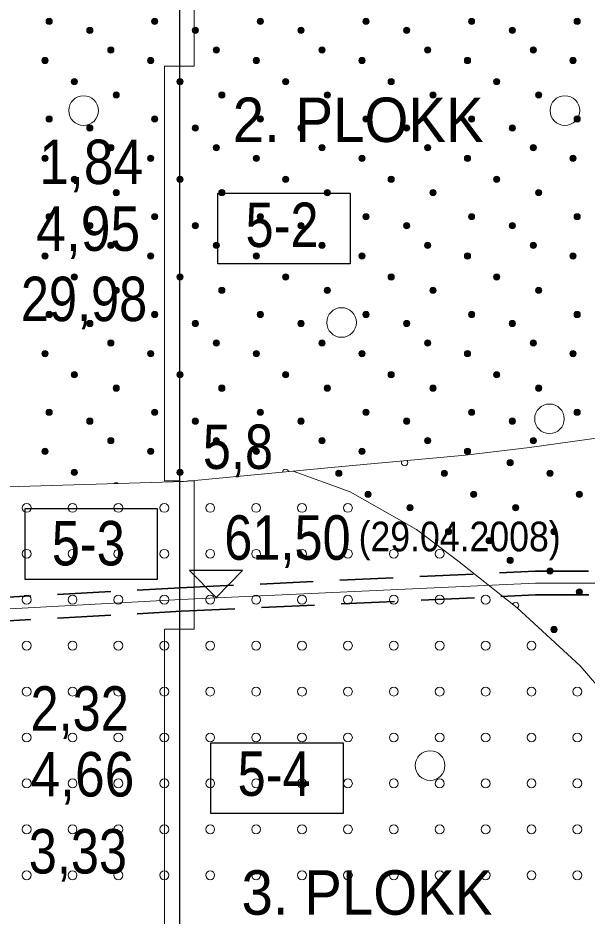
# Model space of a CAD drawing. Extents: x 640121 to 640955, y 6441885 to 6442246.
# Drawn here: x 640200.9 to 640239.3, y 6441932 to 6441992.7 of the extents above; entities that cross this region are included whole.
import ezdxf
from ezdxf.enums import TextEntityAlignment as Align

# ---------------------------------------------------------------- set-up
doc = ezdxf.new("R2010")
doc.units = 0
doc.header["$LTSCALE"] = 1.2
doc.linetypes.add('MEDIUM_DASHED', pattern=[4.5, 3, -1.5])
for name, color, linetype, lineweight in [('31', 7, 'Continuous', 13), ('32', 7, 'Continuous', 13), ('33', 7, 'Continuous', 13), ('34', 7, 'Continuous', 25), ('35', 7, 'Continuous', 35), ('43', 7, 'Continuous', 13), ('44', 7, 'Continuous', 13), ('47', 7, 'Continuous', 13)]:
    doc.layers.add(name, color=color, linetype=linetype, lineweight=lineweight)

msp = doc.modelspace()

# ---------------------------------------------------------------- hatches: boundary and pattern name
at = {"layer": '44'}
for points in [[(640203.218, 6441992.434, 1), (640202.798, 6441992.434, 1)], [(640210.351, 6441992.434, 1), (640209.931, 6441992.434, 1)], [(640217.484, 6441992.434, 1), (640217.064, 6441992.434, 1)], [(640224.617, 6441992.434, 1), (640224.197, 6441992.434, 1)], [(640231.75, 6441992.434, 1), (640231.33, 6441992.434, 1)], [(640238.883, 6441992.434, 1), (640238.463, 6441992.434, 1)], [(640205.965, 6441991.828, 1), (640205.545, 6441991.828, 1)], [(640213.098, 6441991.828, 1), (640212.678, 6441991.828, 1)], [(640220.231, 6441991.828, 1), (640219.811, 6441991.828, 1)], [(640227.364, 6441991.828, 1), (640226.944, 6441991.828, 1)], [(640234.497, 6441991.828, 1), (640234.077, 6441991.828, 1)], [(640207.384, 6441990.506, 1), (640206.964, 6441990.506, 1)], [(640214.517, 6441990.506, 1), (640214.097, 6441990.506, 1)], [(640221.65, 6441990.506, 1), (640221.23, 6441990.506, 1)], [(640228.783, 6441990.506, 1), (640228.363, 6441990.506, 1)], [(640235.916, 6441990.506, 1), (640235.496, 6441990.506, 1)], [(640202.944, 6441989.79, 1), (640202.524, 6441989.79, 1)], [(640210.077, 6441989.79, 1), (640209.657, 6441989.79, 1)], [(640217.21, 6441989.79, 1), (640216.79, 6441989.79, 1)], [(640224.343, 6441989.79, 1), (640223.923, 6441989.79, 1)], [(640231.476, 6441989.79, 1), (640231.056, 6441989.79, 1)], [(640238.609, 6441989.79, 1), (640238.189, 6441989.79, 1)], [(640204.921, 6441988.371, 1), (640204.501, 6441988.371, 1)], [(640212.054, 6441988.371, 1), (640211.634, 6441988.371, 1)], [(640219.187, 6441988.371, 1), (640218.767, 6441988.371, 1)], [(640226.32, 6441988.371, 1), (640225.9, 6441988.371, 1)], [(640233.453, 6441988.371, 1), (640233.033, 6441988.371, 1)], [(640207.748, 6441987.463, 1), (640207.328, 6441987.463, 1)], [(640214.881, 6441987.463, 1), (640214.461, 6441987.463, 1)], [(640222.014, 6441987.463, 1), (640221.594, 6441987.463, 1)], [(640229.147, 6441987.463, 1), (640228.727, 6441987.463, 1)], [(640236.28, 6441987.463, 1), (640235.86, 6441987.463, 1)], [(640203.218, 6441985.838, 1), (640202.798, 6441985.838, 1)], [(640210.351, 6441985.838, 1), (640209.931, 6441985.838, 1)], [(640217.484, 6441985.838, 1), (640217.064, 6441985.838, 1)], [(640224.617, 6441985.838, 1), (640224.197, 6441985.838, 1)], [(640231.75, 6441985.838, 1), (640231.33, 6441985.838, 1)], [(640238.883, 6441985.838, 1), (640238.463, 6441985.838, 1)], [(640205.965, 6441985.232, 1), (640205.545, 6441985.232, 1)], [(640213.098, 6441985.232, 1), (640212.678, 6441985.232, 1)], [(640220.231, 6441985.232, 1), (640219.811, 6441985.232, 1)], [(640227.364, 6441985.232, 1), (640226.944, 6441985.232, 1)], [(640234.497, 6441985.232, 1), (640234.077, 6441985.232, 1)], [(640207.384, 6441983.91, 1), (640206.964, 6441983.91, 1)], [(640214.517, 6441983.91, 1), (640214.097, 6441983.91, 1)], [(640221.65, 6441983.91, 1), (640221.23, 6441983.91, 1)], [(640228.783, 6441983.91, 1), (640228.363, 6441983.91, 1)], [(640235.916, 6441983.91, 1), (640235.496, 6441983.91, 1)], [(640202.944, 6441983.194, 1), (640202.524, 6441983.194, 1)], [(640210.077, 6441983.194, 1), (640209.657, 6441983.194, 1)], [(640217.21, 6441983.194, 1), (640216.79, 6441983.194, 1)], [(640224.343, 6441983.194, 1), (640223.923, 6441983.194, 1)], [(640231.476, 6441983.194, 1), (640231.056, 6441983.194, 1)], [(640238.609, 6441983.194, 1), (640238.189, 6441983.194, 1)], [(640204.921, 6441981.775, 1), (640204.501, 6441981.775, 1)], [(640212.054, 6441981.775, 1), (640211.634, 6441981.775, 1)], [(640219.187, 6441981.775, 1), (640218.767, 6441981.775, 1)], [(640226.32, 6441981.775, 1), (640225.9, 6441981.775, 1)], [(640233.453, 6441981.775, 1), (640233.033, 6441981.775, 1)], [(640207.748, 6441980.867, 1), (640207.328, 6441980.867, 1)], [(640214.881, 6441980.867, 1), (640214.461, 6441980.867, 1)], [(640222.014, 6441980.867, 1), (640221.594, 6441980.867, 1)], [(640229.147, 6441980.867, 1), (640228.727, 6441980.867, 1)], [(640236.28, 6441980.867, 1), (640235.86, 6441980.867, 1)], [(640203.218, 6441979.242, 1), (640202.798, 6441979.242, 1)], [(640210.351, 6441979.242, 1), (640209.931, 6441979.242, 1)], [(640217.484, 6441979.242, 1), (640217.064, 6441979.242, 1)], [(640224.617, 6441979.242, 1), (640224.197, 6441979.242, 1)], [(640231.75, 6441979.242, 1), (640231.33, 6441979.242, 1)], [(640238.883, 6441979.242, 1), (640238.463, 6441979.242, 1)], [(640205.965, 6441978.636, 1), (640205.545, 6441978.636, 1)], [(640213.098, 6441978.636, 1), (640212.678, 6441978.636, 1)], [(640220.231, 6441978.636, 1), (640219.811, 6441978.636, 1)], [(640227.364, 6441978.636, 1), (640226.944, 6441978.636, 1)], [(640234.497, 6441978.636, 1), (640234.077, 6441978.636, 1)], [(640207.384, 6441977.314, 1), (640206.964, 6441977.314, 1)], [(640214.517, 6441977.314, 1), (640214.097, 6441977.314, 1)], [(640221.65, 6441977.314, 1), (640221.23, 6441977.314, 1)], [(640228.783, 6441977.314, 1), (640228.363, 6441977.314, 1)], [(640235.916, 6441977.314, 1), (640235.496, 6441977.314, 1)], [(640202.944, 6441976.598, 1), (640202.524, 6441976.598, 1)], [(640210.077, 6441976.598, 1), (640209.657, 6441976.598, 1)], [(640217.21, 6441976.598, 1), (640216.79, 6441976.598, 1)], [(640224.343, 6441976.598, 1), (640223.923, 6441976.598, 1)], [(640231.476, 6441976.598, 1), (640231.056, 6441976.598, 1)], [(640238.609, 6441976.598, 1), (640238.189, 6441976.598, 1)], [(640204.921, 6441975.179, 1), (640204.501, 6441975.179, 1)], [(640212.054, 6441975.179, 1), (640211.634, 6441975.179, 1)], [(640219.187, 6441975.179, 1), (640218.767, 6441975.179, 1)], [(640226.32, 6441975.179, 1), (640225.9, 6441975.179, 1)], [(640233.453, 6441975.179, 1), (640233.033, 6441975.179, 1)], [(640207.748, 6441974.271, 1), (640207.328, 6441974.271, 1)], [(640214.881, 6441974.271, 1), (640214.461, 6441974.271, 1)], [(640222.014, 6441974.271, 1), (640221.594, 6441974.271, 1)], [(640229.147, 6441974.271, 1), (640228.727, 6441974.271, 1)], [(640236.28, 6441974.271, 1), (640235.86, 6441974.271, 1)], [(640203.218, 6441972.646, 1), (640202.798, 6441972.646, 1)], [(640210.351, 6441972.646, 1), (640209.931, 6441972.646, 1)], [(640217.484, 6441972.646, 1), (640217.064, 6441972.646, 1)], [(640224.617, 6441972.646, 1), (640224.197, 6441972.646, 1)], [(640231.75, 6441972.646, 1), (640231.33, 6441972.646, 1)], [(640238.883, 6441972.646, 1), (640238.463, 6441972.646, 1)], [(640205.965, 6441972.04, 1), (640205.545, 6441972.04, 1)], [(640213.098, 6441972.04, 1), (640212.678, 6441972.04, 1)], [(640220.231, 6441972.04, 1), (640219.811, 6441972.04, 1)], [(640227.364, 6441972.04, 1), (640226.944, 6441972.04, 1)], [(640234.497, 6441972.04, 1), (640234.077, 6441972.04, 1)], [(640207.384, 6441970.718, 1), (640206.964, 6441970.718, 1)], [(640214.517, 6441970.718, 1), (640214.097, 6441970.718, 1)], [(640221.65, 6441970.718, 1), (640221.23, 6441970.718, 1)], [(640228.783, 6441970.718, 1), (640228.363, 6441970.718, 1)], [(640235.916, 6441970.718, 1), (640235.496, 6441970.718, 1)], [(640202.944, 6441970.002, 1), (640202.524, 6441970.002, 1)], [(640210.077, 6441970.002, 1), (640209.657, 6441970.002, 1)], [(640217.21, 6441970.002, 1), (640216.79, 6441970.002, 1)], [(640224.343, 6441970.002, 1), (640223.923, 6441970.002, 1)], [(640231.476, 6441970.002, 1), (640231.056, 6441970.002, 1)], [(640238.609, 6441970.002, 1), (640238.189, 6441970.002, 1)], [(640204.921, 6441968.583, 1), (640204.501, 6441968.583, 1)], [(640212.054, 6441968.583, 1), (640211.634, 6441968.583, 1)], [(640219.187, 6441968.583, 1), (640218.767, 6441968.583, 1)], [(640226.32, 6441968.583, 1), (640225.9, 6441968.583, 1)], [(640233.453, 6441968.583, 1), (640233.033, 6441968.583, 1)], [(640207.748, 6441967.675, 1), (640207.328, 6441967.675, 1)], [(640214.881, 6441967.675, 1), (640214.461, 6441967.675, 1)], [(640222.014, 6441967.675, 1), (640221.594, 6441967.675, 1)], [(640229.147, 6441967.675, 1), (640228.727, 6441967.675, 1)], [(640236.28, 6441967.675, 1), (640235.86, 6441967.675, 1)], [(640203.218, 6441966.05, 1), (640202.798, 6441966.05, 1)], [(640210.351, 6441966.05, 1), (640209.931, 6441966.05, 1)], [(640217.484, 6441966.05, 1), (640217.064, 6441966.05, 1)], [(640224.617, 6441966.05, 1), (640224.197, 6441966.05, 1)], [(640231.75, 6441966.05, 1), (640231.33, 6441966.05, 1)], [(640238.883, 6441966.05, 1), (640238.463, 6441966.05, 1)], [(640205.965, 6441965.444, 1), (640205.545, 6441965.444, 1)], [(640213.098, 6441965.444, 1), (640212.678, 6441965.444, 1)], [(640220.231, 6441965.444, 1), (640219.811, 6441965.444, 1)], [(640227.364, 6441965.444, 1), (640226.944, 6441965.444, 1)], [(640234.497, 6441965.444, 1), (640234.077, 6441965.444, 1)], [(640207.384, 6441964.122, 1), (640206.964, 6441964.122, 1)], [(640214.517, 6441964.122, 1), (640214.097, 6441964.122, 1)], [(640221.65, 6441964.122, 1), (640221.23, 6441964.122, 1)], [(640228.783, 6441964.122, 1), (640228.363, 6441964.122, 1)], [(640235.916, 6441964.122, 1), (640235.496, 6441964.122, 1)], [(640202.944, 6441963.406, 1), (640202.524, 6441963.406, 1)], [(640210.077, 6441963.406, 1), (640209.657, 6441963.406, 1)], [(640217.21, 6441963.406, 1), (640216.79, 6441963.406, 1)], [(640224.343, 6441963.406, 1), (640223.923, 6441963.406, 1)], [(640231.476, 6441963.406, 1), (640231.056, 6441963.406, 1)], [(640234.359, 6441962.648, 1), (640233.939, 6441962.648, 1)], [(640204.921, 6441961.987, 1), (640204.501, 6441961.987, 1)], [(640212.054, 6441961.987, 1), (640211.634, 6441961.987, 1)], [(640222.786, 6441961.932, 1), (640222.366, 6441961.932, 1)], [(640229.919, 6441961.932, 1), (640229.499, 6441961.932, 1)], [(640237.052, 6441961.932, 1), (640236.632, 6441961.932, 1)], [(640224.763, 6441960.513, 1), (640224.343, 6441960.513, 1)], [(640231.896, 6441960.513, 1), (640231.476, 6441960.513, 1)], [(640239.029, 6441960.513, 1), (640238.609, 6441960.513, 1)], [(640227.59, 6441959.605, 1), (640227.17, 6441959.605, 1)], [(640234.723, 6441959.605, 1), (640234.303, 6441959.605, 1)], [(640230.193, 6441957.98, 1), (640229.773, 6441957.98, 1)], [(640237.326, 6441957.98, 1), (640236.906, 6441957.98, 1)], [(640232.94, 6441957.374, 1), (640232.52, 6441957.374, 1)], [(640234.359, 6441956.052, 1), (640233.939, 6441956.052, 1)], [(640237.052, 6441955.336, 1), (640236.632, 6441955.336, 1)], [(640239.029, 6441953.917, 1), (640238.609, 6441953.917, 1)], [(640237.326, 6441951.384, 1), (640236.906, 6441951.384, 1)]]:
    msp.add_hatch(color=256, dxfattribs=at).paths.add_polyline_path(points)

# ---------------------------------------------------------------- linework, layer by layer
at = {"layer": '31'}
for points in [[(640160.01, 6441959.79), (640212.12, 6441961.38), (640223.03, 6441962.4), (640231.14, 6441963.16), (640235.45, 6441963.66), (640242.38, 6441964.64), (640247.49, 6441965.44), (640252.3, 6441966.45), (640254.5, 6441966.85), (640259.39, 6441967.38), (640264.58, 6441967.44), (640269.06, 6441967.32)], [(640219.5, 6441962.07), (640223.33, 6441960.67), (640227.82, 6441958.13), (640230.7, 6441955.94), (640234.62, 6441952.84), (640238.88, 6441948.92), (640244.06, 6441942.93), (640248.32, 6441937.29), (640250.05, 6441934.64), (640251.62, 6441932.26), (640252.58, 6441930.95), (640255.23, 6441927.27), (640257.4, 6441925.27)]]:
    msp.add_lwpolyline(points, dxfattribs=at)
at = {"layer": '32', "lineweight": 25}
msp.add_line((640211.81, 6442019.41), (640211.81, 6441914.41), dxfattribs=at)
at = {"layer": '33'}
for points in [[(640212.81, 6441989.41), (640212.81, 6442011.41), (640211.81, 6442011.41), (640211.81, 6441989.41)], [(640210.81, 6441989.41), (640210.81, 6441961.41), (640211.81, 6441961.41), (640211.81, 6441989.41)], [(640212.81, 6441951.41), (640212.81, 6441961.41), (640212.41, 6441961.41), (640212.12, 6441961.38), (640211.81, 6441961.37), (640211.81, 6441961.37), (640211.81, 6441951.41)], [(640210.81, 6441951.41), (640210.81, 6441929.41), (640211.81, 6441929.41), (640211.81, 6441951.41)]]:
    msp.add_lwpolyline(points, close=True, dxfattribs=at)
at = {"layer": '33', "lineweight": 25}
for points in [[(640214.4, 6441980.84), (640223.33, 6441980.84), (640223.33, 6441976.06), (640214.4, 6441976.06)], [(640201.38, 6441959.54), (640210.3, 6441959.54), (640210.3, 6441954.76), (640201.38, 6441954.76)], [(640213.94, 6441943.74), (640222.86, 6441943.74), (640222.86, 6441938.96), (640213.94, 6441938.96)]]:
    msp.add_lwpolyline(points, close=True, dxfattribs=at)
at = {"layer": '34', "lineweight": 13}
msp.add_lwpolyline([(640160.01, 6441951.16), (640175.15, 6441951.4), (640211.9, 6441953.4), (640235.85, 6441954.52), (640281.21, 6441954.51), (640334.24, 6441954.41), (640399.04, 6441956.94), (640444.67, 6441958.31), (640465.01, 6441958.56)], dxfattribs=at)
at = {"layer": '34'}
msp.add_lwpolyline([(640212.49, 6441955.37), (640214.28, 6441953.55), (640216.06, 6441955.36)], close=True, dxfattribs=at)
at = {"layer": '35', "linetype": 'MEDIUM_DASHED'}
for points in [[(640176.61, 6441952.28), (640211.86, 6441954.2), (640235.83, 6441955.32), (640272.41, 6441955.31)], [(640176.61, 6441950.68), (640211.95, 6441952.61), (640235.86, 6441953.72), (640272.41, 6441953.71)]]:
    msp.add_lwpolyline(points, dxfattribs=at)
at = {"layer": '43'}
for centre in [(640201.488, 6441959.593), (640204.588, 6441959.593), (640207.688, 6441959.593), (640210.788, 6441959.593), (640213.888, 6441959.593), (640216.988, 6441959.593), (640220.088, 6441959.593), (640223.188, 6441959.593), (640201.488, 6441956.493), (640204.588, 6441956.493), (640207.688, 6441956.493), (640210.788, 6441956.493), (640213.888, 6441956.493), (640216.988, 6441956.493), (640220.088, 6441956.493), (640223.188, 6441956.493), (640226.288, 6441956.493), (640229.388, 6441956.493), (640201.488, 6441953.393), (640204.588, 6441953.393), (640207.688, 6441953.393), (640210.788, 6441953.393), (640213.888, 6441953.393), (640216.988, 6441953.393), (640220.088, 6441953.393), (640223.188, 6441953.393), (640226.288, 6441953.393), (640229.388, 6441953.393), (640232.488, 6441953.393), (640201.488, 6441950.293), (640204.588, 6441950.293), (640207.688, 6441950.293), (640210.788, 6441950.293), (640213.888, 6441950.293), (640216.988, 6441950.293), (640220.088, 6441950.293), (640223.188, 6441950.293), (640226.288, 6441950.293), (640229.388, 6441950.293), (640232.488, 6441950.293), (640235.588, 6441950.293), (640201.488, 6441947.193), (640204.588, 6441947.193), (640207.688, 6441947.193), (640210.788, 6441947.193), (640213.888, 6441947.193), (640216.988, 6441947.193), (640220.088, 6441947.193), (640223.188, 6441947.193), (640226.288, 6441947.193), (640229.388, 6441947.193), (640232.488, 6441947.193), (640235.588, 6441947.193), (640238.688, 6441947.193), (640201.488, 6441944.093), (640204.588, 6441944.093), (640207.688, 6441944.093), (640210.788, 6441944.093), (640213.888, 6441944.093), (640216.988, 6441944.093), (640220.088, 6441944.093), (640223.188, 6441944.093), (640226.288, 6441944.093), (640229.388, 6441944.093), (640232.488, 6441944.093), (640235.588, 6441944.093), (640238.688, 6441944.093), (640201.488, 6441940.993), (640204.588, 6441940.993), (640207.688, 6441940.993), (640210.788, 6441940.993), (640213.888, 6441940.993), (640216.988, 6441940.993), (640220.088, 6441940.993), (640223.188, 6441940.993), (640226.288, 6441940.993), (640229.388, 6441940.993), (640232.488, 6441940.993), (640235.588, 6441940.993), (640238.688, 6441940.993), (640201.488, 6441937.893), (640204.588, 6441937.893), (640207.688, 6441937.893), (640210.788, 6441937.893), (640213.888, 6441937.893), (640216.988, 6441937.893), (640220.088, 6441937.893), (640223.188, 6441937.893), (640226.288, 6441937.893), (640229.388, 6441937.893), (640232.488, 6441937.893), (640235.588, 6441937.893), (640238.688, 6441937.893), (640201.488, 6441934.793), (640204.588, 6441934.793), (640207.688, 6441934.793), (640210.788, 6441934.793), (640213.888, 6441934.793), (640216.988, 6441934.793), (640220.088, 6441934.793), (640223.188, 6441934.793), (640226.288, 6441934.793), (640229.388, 6441934.793), (640232.488, 6441934.793), (640235.588, 6441934.793), (640238.688, 6441934.793)]:
    msp.add_circle(centre, 0.3, dxfattribs=at)
at = {"layer": '44'}
for centre in [(640203.008, 6441992.434), (640210.141, 6441992.434), (640217.274, 6441992.434), (640224.407, 6441992.434), (640231.54, 6441992.434), (640238.673, 6441992.434), (640205.755, 6441991.828), (640212.888, 6441991.828), (640220.021, 6441991.828), (640227.154, 6441991.828), (640234.287, 6441991.828), (640207.174, 6441990.506), (640214.307, 6441990.506), (640221.44, 6441990.506), (640228.573, 6441990.506), (640235.706, 6441990.506), (640202.734, 6441989.79), (640209.867, 6441989.79), (640217, 6441989.79), (640224.133, 6441989.79), (640231.266, 6441989.79), (640238.399, 6441989.79), (640204.711, 6441988.371), (640211.844, 6441988.371), (640218.977, 6441988.371), (640226.11, 6441988.371), (640233.243, 6441988.371), (640207.538, 6441987.463), (640214.671, 6441987.463), (640221.804, 6441987.463), (640228.937, 6441987.463), (640236.07, 6441987.463), (640203.008, 6441985.838), (640210.141, 6441985.838), (640217.274, 6441985.838), (640224.407, 6441985.838), (640231.54, 6441985.838), (640238.673, 6441985.838), (640205.755, 6441985.232), (640212.888, 6441985.232), (640220.021, 6441985.232), (640227.154, 6441985.232), (640234.287, 6441985.232), (640207.174, 6441983.91), (640214.307, 6441983.91), (640221.44, 6441983.91), (640228.573, 6441983.91), (640235.706, 6441983.91), (640202.734, 6441983.194), (640209.867, 6441983.194), (640217, 6441983.194), (640224.133, 6441983.194), (640231.266, 6441983.194), (640238.399, 6441983.194), (640204.711, 6441981.775), (640211.844, 6441981.775), (640218.977, 6441981.775), (640226.11, 6441981.775), (640233.243, 6441981.775), (640207.538, 6441980.867), (640214.671, 6441980.867), (640221.804, 6441980.867), (640228.937, 6441980.867), (640236.07, 6441980.867), (640203.008, 6441979.242), (640210.141, 6441979.242), (640217.274, 6441979.242), (640224.407, 6441979.242), (640231.54, 6441979.242), (640238.673, 6441979.242), (640205.755, 6441978.636), (640212.888, 6441978.636), (640220.021, 6441978.636), (640227.154, 6441978.636), (640234.287, 6441978.636), (640207.174, 6441977.314), (640214.307, 6441977.314), (640221.44, 6441977.314), (640228.573, 6441977.314), (640235.706, 6441977.314), (640202.734, 6441976.598), (640209.867, 6441976.598), (640217, 6441976.598), (640224.133, 6441976.598), (640231.266, 6441976.598), (640238.399, 6441976.598), (640204.711, 6441975.179), (640211.844, 6441975.179), (640218.977, 6441975.179), (640226.11, 6441975.179), (640233.243, 6441975.179), (640207.538, 6441974.271), (640214.671, 6441974.271), (640221.804, 6441974.271), (640228.937, 6441974.271), (640236.07, 6441974.271), (640203.008, 6441972.646), (640210.141, 6441972.646), (640217.274, 6441972.646), (640224.407, 6441972.646), (640231.54, 6441972.646), (640238.673, 6441972.646), (640205.755, 6441972.04), (640212.888, 6441972.04), (640220.021, 6441972.04), (640227.154, 6441972.04), (640234.287, 6441972.04), (640207.174, 6441970.718), (640214.307, 6441970.718), (640221.44, 6441970.718), (640228.573, 6441970.718), (640235.706, 6441970.718), (640202.734, 6441970.002), (640209.867, 6441970.002), (640217, 6441970.002), (640224.133, 6441970.002), (640231.266, 6441970.002), (640238.399, 6441970.002), (640204.711, 6441968.583), (640211.844, 6441968.583), (640218.977, 6441968.583), (640226.11, 6441968.583), (640233.243, 6441968.583), (640207.538, 6441967.675), (640214.671, 6441967.675), (640221.804, 6441967.675), (640228.937, 6441967.675), (640236.07, 6441967.675), (640203.008, 6441966.05), (640210.141, 6441966.05), (640217.274, 6441966.05), (640224.407, 6441966.05), (640231.54, 6441966.05), (640238.673, 6441966.05), (640205.755, 6441965.444), (640212.888, 6441965.444), (640220.021, 6441965.444), (640227.154, 6441965.444), (640234.287, 6441965.444), (640207.174, 6441964.122), (640214.307, 6441964.122), (640221.44, 6441964.122), (640228.573, 6441964.122), (640235.706, 6441964.122), (640202.734, 6441963.406), (640209.867, 6441963.406), (640217, 6441963.406), (640224.133, 6441963.406), (640231.266, 6441963.406), (640234.149, 6441962.648), (640204.711, 6441961.987), (640211.844, 6441961.987), (640222.576, 6441961.932), (640229.709, 6441961.932), (640236.842, 6441961.932), (640224.553, 6441960.513), (640231.686, 6441960.513), (640238.819, 6441960.513), (640227.38, 6441959.605), (640234.513, 6441959.605), (640229.983, 6441957.98), (640237.116, 6441957.98), (640232.73, 6441957.374), (640234.149, 6441956.052), (640236.842, 6441955.336), (640238.819, 6441953.917), (640237.116, 6441951.384)]:
    msp.add_circle(centre, 0.21, dxfattribs=at)
for centre, start, end in [((640227.016, 6441962.648), 149.62258, 41.08908), ((640218.977, 6441961.987), 14.28177, 176.34732), ((640207.538, 6441961.079), 53.00813, 130.48771), ((640234.513, 6441953.009), 301.22031, 161.69551)]:
    msp.add_arc(centre, 0.21, start, end, dxfattribs=at)
at = {"layer": '47'}
for centre in [(640205.334, 6441986.41), (640237.844, 6441986.41), (640222.759, 6441972.106), (640236.804, 6441965.604), (640228.741, 6441942.197)]:
    msp.add_circle(centre, 1, dxfattribs=at)

# ---------------------------------------------------------------- texts
at = {"layer": '32'}
for s, width, p in [('1,84', 0.9, (640205.85, 6441981.45)), ('4,95', 0.9, (640205.645, 6441976.94)), ('29,98', 0.85, (640205.365, 6441972.2)), ('5,8', 0.85, (640215.76, 6441962.22)), ('2,32', 0.85, (640205.07, 6441944.55)), ('4,66', 0.9, (640205.255, 6441940.11)), ('3,33', 0.85, (640204.95, 6441934.91))]:
    msp.add_text(s, height=3, dxfattribs=dict(at, width=width)).set_placement(p, align=Align.CENTER)
at = {"layer": '33', "width": 0.85}
for s, p in [('5-2', (640218.74, 6441977.2)), ('5-3', (640205.655, 6441955.71)), ('5-4', (640218.205, 6441940.15))]:
    msp.add_text(s, height=3, dxfattribs=at).set_placement(p, align=Align.CENTER)
at = {"layer": '34'}
for s, height, width, p in [('61,50', 3, 0.85, (640219.105, 6441956.09)), ('(29.04.2008)', 2, 0.9, (640230.735, 6441956.66))]:
    msp.add_text(s, height=height, dxfattribs=dict(at, width=width)).set_placement(p, align=Align.CENTER)
at = {"layer": '35', "width": 0.95}
for s, p in [('2. PLOKK', (640223.88, 6441984.29)), ('3. PLOKK', (640224.475, 6441932.13))]:
    msp.add_text(s, height=3, dxfattribs=at).set_placement(p, align=Align.CENTER)

doc.saveas('drawing.dxf')
